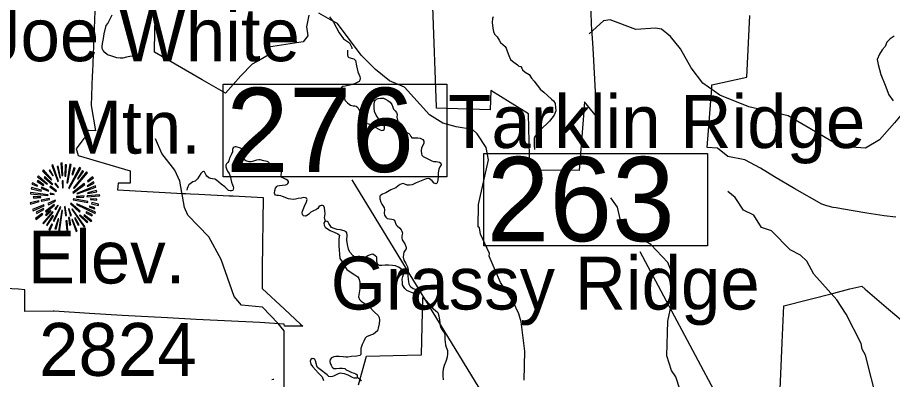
# Model space of a CAD drawing. Extents: x 1159738 to 1321356, y 736314 to 882035.
# Drawn here: x 1191346 to 1205885, y 823694 to 829714 of the extents above; entities that cross this region are included whole.
import ezdxf

# ---------------------------------------------------------------- set-up
doc = ezdxf.new("R2010")
doc.units = 0
for name, color, linetype in [('Exist Boundary Land Use Forest National US Forest Service', 7, 'Continuous'), ('Exist Geographical Mountain Summit CELL', 7, 'Continuous'), ('Exist Geographical Mountain Summit Elevation Number Label', 7, 'Continuous'), ('Exist Geographical Mountain Summit Label', 7, 'Continuous'), ('Exist Hydrographic Creek Single Shore', 7, 'Continuous'), ('Exist Hydrographic Misc Water Feature', 7, 'Continuous'), ('Exist Road Non-System Type 51', 7, 'Continuous'), ('Exist Road Secondary Structure Standard Bridge Number Label', 7, 'Continuous'), ('Exist Road Secondary Type 41 Attributed', 7, 'Continuous')]:
    doc.layers.add(name, color=color, linetype=linetype)

msp = doc.modelspace()

# ---------------------------------------------------------------- linework, layer by layer
at = {"layer": 'Exist Boundary Land Use Forest National US Forest Service'}
for points in [[(1192629, 829820), (1192590, 828809), (1192588, 828752), (1192568, 828249), (1192640, 827831), (1192531, 827832), (1192458, 827832), (1192470, 827731), (1192471, 827725), (1192450, 827699), (1192319, 827531), (1192330, 827494), (1192353, 827420), (1193217, 827165), (1193220, 826961), (1193018, 826960), (1193009, 826849), (1194091, 826789)], [(1200872, 829821), (1200881, 829584), (1200885, 829529), (1200904, 829202), (1200969, 828068), (1200770, 828313), (1200751, 828083), (1200679, 827167), (1199964, 827177), (1199928, 827178), (1199859, 827179), (1199837, 828114), (1199531, 828303), (1199209, 828501), (1199200, 828177), (1198310, 828206), (1198309, 828227), (1198246, 829893)], [(1196188, 829750), (1196149, 829559), (1196168, 829410), (1196092, 829310), (1195515, 829218), (1195511, 829086), (1195378, 829011), (1195243, 828935), (1195055, 828744), (1194803, 828457), (1194412, 828675), (1193624, 829139), (1193625, 829179), (1193634, 829721)], [(1205942, 826396), (1205746, 826418), (1205461, 826459), (1205036, 826533), (1204952, 826548), (1204902, 826557), (1204792, 826581), (1204711, 826610), (1204260, 826866), (1203925, 827067), (1203693, 827207), (1203434, 827345), (1203150, 827402), (1202980, 827543), (1202804, 827552), (1202881, 828537), (1202886, 828594), (1203466, 828724), (1203514, 829749)], [(1194091, 826789), (1194145, 826786), (1194222, 826782), (1194359, 826774), (1194861, 826750), (1194932, 826747), (1195430, 826723), (1195409, 825547), (1195412, 825207), (1195784, 824861), (1196049, 824615), (1196087, 824580), (1195785, 824579), (1195778, 824617), (1195614, 824627), (1195372, 824642), (1194314, 824692), (1193836, 824719), (1193083, 824761), (1192540, 824792), (1191956, 824828), (1191939, 824829), (1191469, 824827), (1191468, 825188), (1191362, 825194), (1190916, 825219)], [(1204009, 823275), (1204054, 824303), (1204054, 824308), (1204079, 824920), (1204909, 825132), (1205179, 825201), (1205376, 825245), (1205431, 825197), (1205820, 824863), (1206239, 824508)], [(1197015, 823605), (1197146, 824084), (1197590, 824094), (1198059, 824105), (1198081, 825059), (1198120, 825026), (1198195, 824941), (1198252, 824872), (1198258, 824867), (1198293, 824839), (1198328, 824810), (1198350, 824755), (1198361, 824683), (1198362, 824647), (1198363, 824617), (1198373, 824567), (1198404, 824522), (1198425, 824489), (1198439, 824465), (1198445, 824421), (1198448, 824362), (1198448, 824359), (1198452, 824315), (1198457, 824272), (1198468, 824232), (1198491, 824175), (1198493, 824121), (1198484, 824063), (1198466, 823994), (1198438, 823925), (1198418, 823865), (1198413, 823815), (1198415, 823753), (1198418, 823689)]]:
    msp.add_lwpolyline(points, dxfattribs=at)
at = {"layer": 'Exist Geographical Mountain Summit CELL'}
for points in [[(1192068, 827292), (1192084, 827084), (1192097, 827086), (1192091, 827296)], [(1191760, 827161), (1191904, 827012), (1191917, 827022), (1191776, 827180)], [(1191870, 827167), (1191933, 827080), (1191940, 827086), (1191886, 827183)], [(1191914, 827254), (1192018, 826987), (1192030, 826991), (1191934, 827264)], [(1192049, 827046), (1192059, 827049), (1192023, 827241), (1192005, 827237)], [(1192132, 827076), (1192148, 827076), (1192162, 827264), (1192140, 827264)], [(1192180, 826962), (1192239, 827270), (1192218, 827277), (1192167, 826965)], [(1192193, 826875), (1192205, 826868), (1192399, 827206), (1192377, 827221)], [(1192251, 827103), (1192264, 827098), (1192302, 827206), (1192283, 827213)], [(1192277, 826881), (1192286, 826872), (1192508, 827129), (1192492, 827148)], [(1192427, 827167), (1192343, 827033), (1192354, 827029), (1192444, 827154)], [(1191674, 826987), (1191777, 826921), (1191786, 826932), (1191685, 827003)], [(1191678, 827062), (1191837, 826940), (1191846, 826949), (1191693, 827080)], [(1191792, 827051), (1191922, 826934), (1191931, 826943), (1191803, 827071)], [(1192090, 826999), (1192095, 826882), (1192106, 826883), (1192106, 827000)], [(1192508, 826993), (1192516, 826983), (1192607, 827048), (1192593, 827062)], [(1191575, 826866), (1191741, 826828), (1191745, 826841), (1191580, 826885)], [(1191587, 826943), (1191677, 826908), (1191681, 826920), (1191593, 826964)], [(1191741, 826875), (1191863, 826827), (1191867, 826835), (1191750, 826891)], [(1191886, 826897), (1191987, 826821), (1191995, 826833), (1191896, 826910)], [(1191965, 826949), (1192020, 826883), (1192028, 826892), (1191978, 826961)], [(1192264, 826801), (1192271, 826791), (1192466, 826934), (1192453, 826952)], [(1192332, 826789), (1192337, 826780), (1192649, 826895), (1192642, 826914)], [(1192508, 826901), (1192619, 826961), (1192607, 826981), (1192503, 826911)], [(1191565, 826782), (1191853, 826754), (1191854, 826766), (1191565, 826802)], [(1191613, 826712), (1191732, 826718), (1191732, 826732), (1191609, 826732)], [(1191742, 826676), (1191747, 826657), (1191879, 826690), (1191876, 826705)], [(1191887, 826777), (1191956, 826769), (1191958, 826777), (1191891, 826795)], [(1192328, 826738), (1192328, 826727), (1192449, 826727), (1192452, 826747)], [(1192501, 826734), (1192710, 826747), (1192712, 826766), (1192503, 826747)], [(1192516, 826789), (1192663, 826815), (1192657, 826837), (1192510, 826798)], [(1191559, 826631), (1191565, 826610), (1191709, 826653), (1191700, 826665)], [(1191598, 826520), (1191609, 826501), (1191790, 826581), (1191784, 826600)], [(1191813, 826494), (1191825, 826479), (1191963, 826593), (1191956, 826603)], [(1191853, 826619), (1191862, 826600), (1191976, 826661), (1191972, 826674)], [(1191940, 826334), (1191958, 826327), (1192064, 826561), (1192053, 826564)], [(1191968, 826532), (1191981, 826520), (1192021, 826586), (1192014, 826591)], [(1192127, 826568), (1192143, 826420), (1192161, 826421), (1192140, 826571)], [(1192225, 826615), (1192379, 826474), (1192389, 826491), (1192232, 826624)], [(1192270, 826683), (1192513, 826635), (1192517, 826653), (1192274, 826698)], [(1192325, 826605), (1192638, 826452), (1192645, 826474), (1192331, 826616)], [(1192539, 826564), (1192623, 826532), (1192630, 826549), (1192545, 826577)], [(1192561, 826686), (1192667, 826677), (1192667, 826694), (1192562, 826699)], [(1192577, 826617), (1192690, 826588), (1192693, 826610), (1192581, 826635)], [(1191643, 826373), (1191655, 826357), (1191768, 826442), (1191758, 826455)], [(1191668, 826456), (1191784, 826523), (1191776, 826538), (1191659, 826476)], [(1191767, 826295), (1191779, 826285), (1191941, 826475), (1191930, 826484)], [(1191828, 826420), (1191905, 826492), (1191892, 826501), (1191810, 826433)], [(1191927, 826420), (1191827, 826263), (1191839, 826253), (1191943, 826411)], [(1192026, 826153), (1192044, 826148), (1192095, 826505), (1192082, 826509)], [(1192192, 826533), (1192226, 826414), (1192242, 826421), (1192200, 826538)], [(1192250, 826524), (1192452, 826225), (1192466, 826237), (1192260, 826529)], [(1192379, 826421), (1192499, 826305), (1192513, 826315), (1192388, 826431)], [(1192446, 826424), (1192568, 826321), (1192581, 826335), (1192453, 826434)], [(1192482, 826468), (1192582, 826416), (1192593, 826430), (1192491, 826484)], [(1191867, 826186), (1191886, 826174), (1191930, 826273), (1191917, 826282)], [(1191987, 826193), (1192034, 826364), (1192020, 826366), (1191969, 826197)], [(1192152, 826334), (1192167, 826164), (1192183, 826168), (1192169, 826334)], [(1192231, 826267), (1192209, 826387), (1192196, 826387), (1192213, 826263)], [(1192250, 826353), (1192319, 826154), (1192337, 826161), (1192261, 826356)], [(1192292, 826376), (1192356, 826258), (1192372, 826267), (1192306, 826382)]]:
    msp.add_lwpolyline(points, close=True, dxfattribs=at)
at = {"layer": 'Exist Hydrographic Creek Single Shore'}
for points in [[(1199764, 823683), (1199777, 824168), (1199715, 824652), (1199677, 824788), (1199582, 824983), (1199374, 825306), (1199186, 825743), (1199187, 825792), (1199037, 826113), (1199024, 826215), (1198999, 826232), (1199009, 826606), (1199171, 827345), (1199135, 827552), (1198982, 827782), (1198909, 827852), (1198635, 827894), (1198412, 827958), (1198190, 828097), (1197778, 828558), (1197529, 828658), (1197293, 828847), (1197057, 829088), (1196663, 829614), (1196548, 829676), (1196351, 829786)], [(1206207, 828293), (1206059, 828126), (1205917, 827962), (1205668, 827678), (1205439, 827541), (1205206, 827556), (1204899, 827641), (1204152, 828076), (1203498, 828227), (1203019, 828423), (1202733, 828623), (1202540, 828879), (1202365, 829191), (1202195, 829398), (1202048, 829520), (1201949, 829538), (1201623, 829512), (1201194, 829674), (1201085, 829660), (1200845, 829442)], [(1205912, 829402), (1205847, 829359), (1205793, 829305), (1205764, 829230), (1205713, 829175), (1205669, 829105), (1205633, 829013), (1205645, 828933), (1205689, 828766), (1205763, 828587), (1205827, 828429), (1205899, 828327)], [(1195775, 823559), (1195775, 824501), (1195678, 824628), (1195419, 824896), (1195069, 824929), (1194948, 825073), (1194731, 825687), (1194525, 826069), (1194176, 826427), (1194120, 826556), (1194041, 826991), (1193963, 827177), (1193744, 827450), (1193642, 827695)]]:
    msp.add_lwpolyline(points, dxfattribs=at)
at = {"layer": 'Exist Hydrographic Misc Water Feature'}
for points in [[(1202422, 823311), (1202284, 823741), (1202212, 823844), (1202135, 824088), (1202150, 824663), (1202226, 825002), (1202230, 825445), (1202152, 825637), (1201868, 825939), (1201458, 826190), (1201385, 826267), (1201318, 826560), (1201205, 826713)], [(1205633, 823332), (1205437, 824098), (1205382, 824201), (1205367, 824293), (1205114, 824780), (1204962, 825020), (1204581, 825448), (1204462, 825660), (1204356, 825761), (1204184, 825850), (1203876, 826168), (1203710, 826220), (1203582, 826426), (1203410, 826512), (1203273, 826718), (1203151, 826819)]]:
    msp.add_lwpolyline(points, dxfattribs=at)
at = {"layer": 'Exist Road Non-System Type 51'}
for p, q in [((1196992, 823730), (1196992, 823730)), ((1197018, 823712), (1197018, 823712))]:
    msp.add_line(p, q, dxfattribs=at)
for points in [[(1193406, 829113), (1193356, 829096), (1193302, 829074), (1193268, 829070), (1193212, 829064), (1193155, 829054), (1193099, 829039), (1193053, 829035), (1192996, 829041), (1192895, 829074), (1192842, 829094), (1192800, 829130), (1192772, 829167), (1192754, 829200), (1192754, 829230), (1192760, 829284), (1192776, 829366), (1192785, 829442), (1192819, 829579), (1192847, 829613), (1192864, 829645), (1192918, 829757)], [(1199250, 829727), (1199238, 829697), (1199236, 829629), (1199243, 829539), (1199255, 829483), (1199274, 829438), (1199317, 829393), (1199347, 829334), (1199371, 829296), (1199448, 829233), (1199468, 829204), (1199481, 829155), (1199508, 829082), (1199536, 829017), (1199569, 828987), (1199654, 828925), (1199676, 828906), (1199711, 828899), (1199725, 828873), (1199735, 828845), (1199784, 828807), (1199848, 828765), (1199886, 828704), (1199929, 828657), (1199961, 828615), (1200002, 828563), (1200032, 828521), (1200093, 828474), (1200155, 828414), (1200219, 828358), (1200252, 828327), (1200278, 828283), (1200287, 828217), (1200290, 828160), (1200266, 828087), (1200188, 827991), (1200030, 827838), (1199968, 827770), (1199943, 827735), (1199933, 827701), (1199929, 827650), (1199933, 827588), (1199935, 827520)], [(1196828, 829168), (1196827, 829127), (1196830, 829092), (1196835, 829067), (1196853, 829049), (1196914, 829033), (1196935, 829027), (1196960, 828997), (1196980, 828910), (1196999, 828812), (1197018, 828770), (1197036, 828732), (1197042, 828699), (1197034, 828674), (1197021, 828650), (1196991, 828631), (1196947, 828609), (1196861, 828590), (1196789, 828574), (1196751, 828564), (1196727, 828543), (1196723, 828498), (1196730, 828463), (1196761, 828436), (1196774, 828392), (1196786, 828341), (1196808, 828316), (1196830, 828296), (1196859, 828271), (1196882, 828258), (1196923, 828246), (1196954, 828246), (1196973, 828242), (1197001, 828216), (1197030, 828159), (1197062, 828093), (1197081, 828017), (1197099, 827980), (1197117, 827966), (1197148, 827953), (1197176, 827947), (1197216, 827932), (1197262, 827906), (1197338, 827865), (1197381, 827840), (1197398, 827836), (1197425, 827838), (1197439, 827853), (1197445, 827866), (1197447, 827901), (1197422, 827939), (1197385, 827998), (1197341, 828038), (1197305, 828090), (1197278, 828152), (1197270, 828213), (1197271, 828268), (1197276, 828317), (1197287, 828335), (1197312, 828358), (1197338, 828369), (1197376, 828373), (1197426, 828370), (1197460, 828358), (1197502, 828332), (1197539, 828304), (1197564, 828265), (1197581, 828222), (1197595, 828187), (1197622, 828159), (1197644, 828134), (1197653, 828098), (1197652, 828058), (1197659, 828008), (1197682, 827951), (1197725, 827896), (1197767, 827840), (1197805, 827809), (1197848, 827783), (1197866, 827766), (1197884, 827735), (1197900, 827714), (1197948, 827710), (1198001, 827712), (1198035, 827707), (1198080, 827687), (1198097, 827657), (1198100, 827625), (1198081, 827586), (1198059, 827548), (1198054, 827496), (1198059, 827446), (1198065, 827426), (1198089, 827403), (1198153, 827369), (1198231, 827333), (1198258, 827321), (1198303, 827318), (1198330, 827315), (1198357, 827307), (1198381, 827289)], [(1195074, 827532), (1195052, 827543), (1194981, 827564), (1194963, 827564), (1194944, 827559), (1194930, 827544), (1194921, 827516), (1194918, 827482), (1194902, 827440), (1194871, 827374), (1194856, 827333), (1194841, 827304), (1194821, 827281), (1194810, 827258), (1194810, 827232), (1194817, 827200), (1194838, 827158), (1194864, 827120), (1194879, 827076), (1194902, 826974), (1194919, 826930), (1194930, 826902), (1194933, 826882), (1194930, 826859), (1194923, 826839), (1194901, 826829), (1194878, 826830), (1194853, 826835), (1194840, 826849), (1194790, 826897), (1194730, 826944), (1194652, 827010), (1194627, 827023), (1194587, 827030), (1194558, 827035), (1194528, 827047), (1194495, 827075), (1194479, 827093), (1194456, 827145), (1194448, 827152), (1194436, 827154), (1194418, 827145), (1194395, 827119), (1194367, 827076), (1194336, 827033), (1194317, 827008), (1194296, 826994), (1194259, 826980), (1194217, 826949), (1194192, 826929), (1194175, 826900), (1194167, 826870), (1194162, 826843)], [(1196465, 826326), (1196454, 826359), (1196450, 826387), (1196455, 826411), (1196459, 826455), (1196455, 826500), (1196445, 826547), (1196437, 826576), (1196430, 826581), (1196413, 826588), (1196412, 826588), (1196390, 826589), (1196376, 826584), (1196353, 826564), (1196334, 826540), (1196302, 826517), (1196275, 826507), (1196222, 826475), (1196188, 826446), (1196149, 826418), (1196138, 826413), (1196124, 826409), (1196101, 826413), (1196089, 826428), (1196082, 826441), (1196075, 826468), (1196082, 826495), (1196117, 826577), (1196148, 826648), (1196159, 826685), (1196156, 826700), (1196146, 826709), (1196133, 826717), (1196099, 826720), (1196059, 826712), (1196010, 826702), (1195968, 826692), (1195939, 826688), (1195887, 826692), (1195847, 826699), (1195751, 826736), (1195721, 826748), (1195684, 826753), (1195656, 826755), (1195635, 826762), (1195621, 826774), (1195615, 826795), (1195621, 826839), (1195635, 826875), (1195658, 826905), (1195667, 826914), (1195697, 826921), (1195749, 826924), (1195805, 826933), (1195827, 826943), (1195838, 826954), (1195847, 826970), (1195847, 826987), (1195837, 827006), (1195813, 827019), (1195743, 827054), (1195732, 827070), (1195726, 827093), (1195732, 827135), (1195740, 827174), (1195747, 827196), (1195743, 827210), (1195732, 827224), (1195708, 827232), (1195670, 827227), (1195637, 827208), (1195601, 827183), (1195582, 827168), (1195562, 827161), (1195538, 827162), (1195520, 827174), (1195508, 827188), (1195507, 827200), (1195509, 827222), (1195520, 827242), (1195530, 827264), (1195531, 827280), (1195526, 827296), (1195516, 827307), (1195494, 827321), (1195441, 827333), (1195380, 827349), (1195355, 827349), (1195319, 827340), (1195252, 827317), (1195230, 827312), (1195193, 827316), (1195143, 827331), (1195119, 827345), (1195103, 827361), (1195086, 827391), (1195078, 827423), (1195080, 827455), (1195083, 827497), (1195083, 827516), (1195074, 827532)], [(1198381, 827289), (1198384, 827261), (1198366, 827229), (1198346, 827194), (1198334, 827129), (1198334, 827071), (1198331, 827008), (1198321, 826965), (1198302, 826949), (1198270, 826961), (1198237, 826995), (1198193, 827031), (1198170, 827037), (1198135, 827031), (1198056, 826996), (1197971, 826964), (1197905, 826933), (1197858, 826927), (1197819, 826927), (1197785, 826941), (1197756, 826951), (1197732, 826948), (1197703, 826935), (1197673, 826915), (1197631, 826882), (1197548, 826846), (1197469, 826800), (1197410, 826777), (1197381, 826762), (1197368, 826740), (1197369, 826701), (1197381, 826641), (1197398, 826610), (1197423, 826578), (1197439, 826549), (1197442, 826513), (1197441, 826462), (1197445, 826426), (1197466, 826391), (1197488, 826374), (1197527, 826365), (1197567, 826362), (1197589, 826356), (1197609, 826341), (1197625, 826296), (1197640, 826268), (1197657, 826248), (1197698, 826208), (1197723, 826182), (1197732, 826161), (1197742, 826126), (1197735, 826084), (1197733, 826050), (1197739, 826019), (1197782, 825948), (1197801, 825907), (1197804, 825894), (1197802, 825869), (1197789, 825847), (1197764, 825813), (1197758, 825780), (1197755, 825727), (1197767, 825679), (1197801, 825623), (1197828, 825565), (1197836, 825512), (1197834, 825420), (1197837, 825360), (1197842, 825316), (1197849, 825284), (1197864, 825252), (1197884, 825233), (1197922, 825209), (1197973, 825189), (1198007, 825173), (1198023, 825160), (1198027, 825142), (1198022, 825123), (1198001, 825109), (1197969, 825107), (1197918, 825129), (1197818, 825176), (1197783, 825208), (1197758, 825239), (1197742, 825268), (1197742, 825305), (1197739, 825365), (1197748, 825406), (1197761, 825438), (1197758, 825459), (1197741, 825503), (1197719, 825535), (1197679, 825561), (1197629, 825583), (1197575, 825589), (1197511, 825598), (1197457, 825594), (1197400, 825589), (1197364, 825589), (1197348, 825596), (1197328, 825618)], [(1196465, 826326), (1196451, 826320), (1196439, 826296), (1196442, 826258), (1196458, 826226), (1196495, 826198), (1196540, 826172), (1196607, 826144), (1196669, 826119), (1196694, 826096), (1196686, 826031), (1196688, 825918), (1196702, 825705), (1196730, 825666), (1196771, 825610), (1196795, 825559), (1196817, 825521), (1196875, 825484), (1196953, 825436), (1197001, 825401), (1197017, 825375), (1197036, 825318), (1197036, 825240), (1197036, 825201), (1197015, 825070), (1197029, 825027), (1197059, 824996), (1197192, 824906), (1197270, 824822), (1197340, 824758), (1197355, 824726), (1197359, 824679), (1197355, 824622), (1197340, 824548), (1197327, 824502), (1197296, 824473), (1197262, 824449), (1197213, 824429), (1197148, 824404), (1197123, 824382), (1197100, 824332), (1197072, 824274), (1197050, 824209), (1197052, 824138), (1197052, 824111), (1197034, 824092), (1196986, 824080), (1196898, 824075), (1196835, 824068), (1196803, 824065), (1196759, 824070), (1196690, 824075), (1196638, 824077), (1196601, 824071), (1196564, 824053), (1196541, 824026), (1196538, 823998), (1196544, 823963), (1196556, 823930), (1196573, 823901), (1196600, 823878), (1196642, 823879), (1196695, 823881), (1196742, 823882), (1196785, 823876), (1196809, 823857), (1196859, 823832), (1196903, 823813), (1196938, 823799), (1196969, 823787), (1196988, 823770), (1196992, 823752), (1196992, 823730)], [(1197328, 825618), (1197318, 825654), (1197315, 825703), (1197315, 825726), (1197287, 825753), (1197248, 825777), (1197221, 825774), (1197179, 825756), (1197115, 825717), (1197063, 825698), (1197018, 825696), (1196986, 825705), (1196964, 825717), (1196926, 825752), (1196869, 825811), (1196844, 825862), (1196832, 825938), (1196820, 826010), (1196825, 826096), (1196817, 826135), (1196808, 826147), (1196774, 826165), (1196714, 826181), (1196660, 826188), (1196606, 826203), (1196565, 826223), (1196550, 826238), (1196522, 826289), (1196506, 826311), (1196492, 826324), (1196465, 826326)], [(1196992, 823730), (1196978, 823718), (1196941, 823717), (1196912, 823726), (1196843, 823768), (1196782, 823787), (1196743, 823794), (1196708, 823797), (1196673, 823790), (1196607, 823756), (1196580, 823743), (1196543, 823740), (1196522, 823745), (1196489, 823771), (1196378, 823859), (1196332, 823896), (1196319, 823919), (1196300, 824002), (1196288, 824029), (1196269, 824039), (1196241, 824041), (1196218, 824029), (1196212, 823998), (1196222, 823950), (1196247, 823912), (1196350, 823802), (1196407, 823736), (1196433, 823680)], [(1195606, 823693), (1195594, 823697), (1195575, 823690)], [(1196992, 823730), (1197009, 823723), (1197032, 823699), (1197059, 823669)]]:
    msp.add_lwpolyline(points, dxfattribs=at)
at = {"layer": 'Exist Road Secondary Structure Standard Bridge Number Label'}
for p, q in [((1201916, 818803), (1196908, 827013)), ((1204661, 820254), (1201694, 825818))]:
    msp.add_line(p, q, dxfattribs=at)
for points in [[(1194763, 828603), (1198479, 828603), (1198479, 827066), (1194763, 827066)], [(1199094, 827451), (1202810, 827451), (1202810, 825915), (1199094, 825915)]]:
    msp.add_lwpolyline(points, close=True, dxfattribs=at)
at = {"layer": 'Exist Road Secondary Type 41 Attributed'}
msp.add_lwpolyline([(1196530, 829726), (1196596, 829634), (1196689, 829457), (1196764, 829361), (1196862, 829292), (1196900, 829217), (1196899, 829194)], dxfattribs=at)

# ---------------------------------------------------------------- texts
at = {"layer": 'Exist Geographical Mountain Summit Elevation Number Label'}
for s, p in [('Elev.', (1191519, 825291)), (' 2824', (1191378, 823755))]:
    msp.add_text(s, height=880, dxfattribs=at).set_placement(p)
at = {"layer": 'Exist Geographical Mountain Summit Label'}
for s, p in [('Joe White', (1190808, 828987)), ('Tarklin Ridge', (1198502, 827544)), (' Mtn.', (1191777, 827450)), ('Grassy Ridge', (1196551, 824858))]:
    msp.add_text(s, height=880, dxfattribs=at).set_placement(p)
at = {"layer": 'Exist Road Secondary Structure Standard Bridge Number Label'}
for s, p in [('276', (1194813, 827145)), ('263', (1199144, 825994))]:
    msp.add_text(s, height=1400, dxfattribs=at).set_placement(p)

doc.saveas('drawing.dxf')
